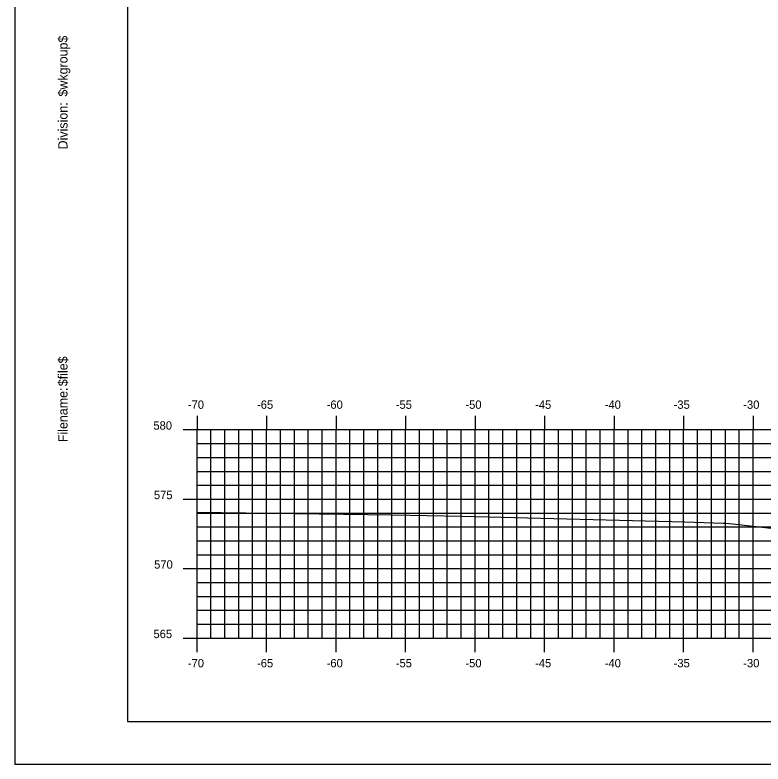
# Model space of a CAD drawing. Extents: x 1048552 to 1048722, y 781630 to 781740.
# Drawn here: x 1048552.2 to 1048606, y 781630.1 to 781684 of the extents above; entities that cross this region are included whole.
import ezdxf

# ---------------------------------------------------------------- set-up
doc = ezdxf.new("R2010")
doc.units = 0
for name, color, linetype in [('Default', 7, 'Continuous'), ('H_V ANNOTATION', 7, 'Continuous'), ('MAJOR', 7, 'Continuous'), ('MINOR', 7, 'Continuous'), ('S_Roadway_Centerline', 7, 'Continuous')]:
    doc.layers.add(name, color=color, linetype=linetype)

msp = doc.modelspace()

# ---------------------------------------------------------------- linework, layer by layer
at = {"layer": 'Default'}
for p, q in [((1048560.247, 781738.195), (1048560.247, 781633.195)), ((1048560.247, 781633.195), (1048720.247, 781633.195))]:
    msp.add_line(p, q, dxfattribs=at)
msp.add_lwpolyline([(1048552.153, 781630.136), (1048722.153, 781630.136), (1048722.153, 781740.136), (1048552.153, 781740.136)], close=True, dxfattribs=at)
at = {"layer": 'MAJOR'}
for p, q in [((1048565.246, 781655.197), (1048565.246, 781654.195)), ((1048565.246, 781655.197), (1048565.246, 781654.195)), ((1048570.246, 781655.197), (1048570.246, 781654.195)), ((1048570.246, 781655.197), (1048570.246, 781654.195)), ((1048575.246, 781655.197), (1048575.246, 781654.195)), ((1048575.246, 781655.197), (1048575.246, 781654.195)), ((1048580.246, 781655.197), (1048580.246, 781654.195)), ((1048580.246, 781655.197), (1048580.246, 781654.195)), ((1048585.246, 781655.197), (1048585.246, 781654.195)), ((1048585.246, 781655.197), (1048585.246, 781654.195)), ((1048590.246, 781655.197), (1048590.246, 781654.195)), ((1048590.246, 781655.197), (1048590.246, 781654.195)), ((1048595.246, 781655.197), (1048595.246, 781654.195)), ((1048595.246, 781655.197), (1048595.246, 781654.195)), ((1048600.246, 781655.197), (1048600.246, 781654.195)), ((1048600.246, 781655.197), (1048600.246, 781654.195)), ((1048605.246, 781655.197), (1048605.246, 781654.195)), ((1048605.246, 781655.197), (1048605.246, 781654.195)), ((1048564.244, 781654.195), (1048565.246, 781654.195)), ((1048564.244, 781654.195), (1048565.246, 781654.195)), ((1048565.246, 781654.195), (1048705.246, 781654.195)), ((1048565.246, 781639.195), (1048565.246, 781654.195)), ((1048565.246, 781639.195), (1048565.246, 781654.195)), ((1048565.246, 781654.195), (1048705.246, 781654.195)), ((1048565.246, 781654.195), (1048705.246, 781654.195)), ((1048565.246, 781639.195), (1048565.246, 781654.195)), ((1048565.246, 781639.195), (1048565.246, 781654.195)), ((1048565.246, 781654.195), (1048705.246, 781654.195)), ((1048570.246, 781639.195), (1048570.246, 781654.195)), ((1048570.246, 781639.195), (1048570.246, 781654.195)), ((1048575.246, 781639.195), (1048575.246, 781654.195)), ((1048575.246, 781639.195), (1048575.246, 781654.195)), ((1048580.246, 781639.195), (1048580.246, 781654.195)), ((1048580.246, 781639.195), (1048580.246, 781654.195)), ((1048585.246, 781639.195), (1048585.246, 781654.195)), ((1048585.246, 781639.195), (1048585.246, 781654.195)), ((1048590.246, 781639.195), (1048590.246, 781654.195)), ((1048590.246, 781639.195), (1048590.246, 781654.195)), ((1048595.246, 781639.195), (1048595.246, 781654.195)), ((1048595.246, 781639.195), (1048595.246, 781654.195)), ((1048600.246, 781639.195), (1048600.246, 781654.195)), ((1048600.246, 781639.195), (1048600.246, 781654.195)), ((1048605.246, 781639.195), (1048605.246, 781654.195)), ((1048605.246, 781639.195), (1048605.246, 781654.195)), ((1048564.244, 781649.195), (1048565.246, 781649.195)), ((1048564.244, 781649.195), (1048565.246, 781649.195)), ((1048565.246, 781649.195), (1048705.246, 781649.195)), ((1048565.246, 781649.195), (1048705.246, 781649.195)), ((1048564.244, 781644.195), (1048565.246, 781644.195)), ((1048564.244, 781644.195), (1048565.246, 781644.195)), ((1048565.246, 781644.195), (1048705.246, 781644.195)), ((1048565.246, 781644.195), (1048705.246, 781644.195)), ((1048564.244, 781639.195), (1048565.246, 781639.195)), ((1048564.244, 781639.195), (1048565.246, 781639.195)), ((1048565.246, 781639.195), (1048705.246, 781639.195)), ((1048565.246, 781639.195), (1048705.246, 781639.195)), ((1048565.246, 781638.193), (1048565.246, 781639.195)), ((1048565.246, 781639.195), (1048705.246, 781639.195)), ((1048565.246, 781639.195), (1048705.246, 781639.195)), ((1048565.246, 781638.193), (1048565.246, 781639.195)), ((1048570.246, 781638.193), (1048570.246, 781639.195)), ((1048570.246, 781638.193), (1048570.246, 781639.195)), ((1048575.246, 781638.193), (1048575.246, 781639.195)), ((1048575.246, 781638.193), (1048575.246, 781639.195)), ((1048580.246, 781638.193), (1048580.246, 781639.195)), ((1048580.246, 781638.193), (1048580.246, 781639.195)), ((1048585.246, 781638.193), (1048585.246, 781639.195)), ((1048585.246, 781638.193), (1048585.246, 781639.195)), ((1048590.246, 781638.193), (1048590.246, 781639.195)), ((1048590.246, 781638.193), (1048590.246, 781639.195)), ((1048595.246, 781638.193), (1048595.246, 781639.195)), ((1048595.246, 781638.193), (1048595.246, 781639.195)), ((1048600.246, 781638.193), (1048600.246, 781639.195)), ((1048600.246, 781638.193), (1048600.246, 781639.195)), ((1048605.246, 781638.193), (1048605.246, 781639.195)), ((1048605.246, 781638.193), (1048605.246, 781639.195))]:
    msp.add_line(p, q, dxfattribs=at)
at = {"layer": 'MINOR'}
for p, q in [((1048566.246, 781639.195), (1048566.246, 781654.195)), ((1048566.246, 781639.195), (1048566.246, 781654.195)), ((1048567.246, 781639.195), (1048567.246, 781654.195)), ((1048567.246, 781639.195), (1048567.246, 781654.195)), ((1048568.246, 781639.195), (1048568.246, 781654.195)), ((1048568.246, 781639.195), (1048568.246, 781654.195)), ((1048569.246, 781639.195), (1048569.246, 781654.195)), ((1048569.246, 781639.195), (1048569.246, 781654.195)), ((1048571.246, 781639.195), (1048571.246, 781654.195)), ((1048571.246, 781639.195), (1048571.246, 781654.195)), ((1048572.246, 781639.195), (1048572.246, 781654.195)), ((1048572.246, 781639.195), (1048572.246, 781654.195)), ((1048573.246, 781639.195), (1048573.246, 781654.195)), ((1048573.246, 781639.195), (1048573.246, 781654.195)), ((1048574.246, 781639.195), (1048574.246, 781654.195)), ((1048574.246, 781639.195), (1048574.246, 781654.195)), ((1048576.246, 781639.195), (1048576.246, 781654.195)), ((1048576.246, 781639.195), (1048576.246, 781654.195)), ((1048577.246, 781639.195), (1048577.246, 781654.195)), ((1048577.246, 781639.195), (1048577.246, 781654.195)), ((1048578.246, 781639.195), (1048578.246, 781654.195)), ((1048578.246, 781639.195), (1048578.246, 781654.195)), ((1048579.246, 781639.195), (1048579.246, 781654.195)), ((1048579.246, 781639.195), (1048579.246, 781654.195)), ((1048581.246, 781639.195), (1048581.246, 781654.195)), ((1048581.246, 781639.195), (1048581.246, 781654.195)), ((1048582.246, 781639.195), (1048582.246, 781654.195)), ((1048582.246, 781639.195), (1048582.246, 781654.195)), ((1048583.246, 781639.195), (1048583.246, 781654.195)), ((1048583.246, 781639.195), (1048583.246, 781654.195)), ((1048584.246, 781639.195), (1048584.246, 781654.195)), ((1048584.246, 781639.195), (1048584.246, 781654.195)), ((1048586.246, 781639.195), (1048586.246, 781654.195)), ((1048586.246, 781639.195), (1048586.246, 781654.195)), ((1048587.246, 781639.195), (1048587.246, 781654.195)), ((1048587.246, 781639.195), (1048587.246, 781654.195)), ((1048588.246, 781639.195), (1048588.246, 781654.195)), ((1048588.246, 781639.195), (1048588.246, 781654.195)), ((1048589.246, 781639.195), (1048589.246, 781654.195)), ((1048589.246, 781639.195), (1048589.246, 781654.195)), ((1048591.246, 781639.195), (1048591.246, 781654.195)), ((1048591.246, 781639.195), (1048591.246, 781654.195)), ((1048592.246, 781639.195), (1048592.246, 781654.195)), ((1048592.246, 781639.195), (1048592.246, 781654.195)), ((1048593.246, 781639.195), (1048593.246, 781654.195)), ((1048593.246, 781639.195), (1048593.246, 781654.195)), ((1048594.246, 781639.195), (1048594.246, 781654.195)), ((1048594.246, 781639.195), (1048594.246, 781654.195)), ((1048596.246, 781639.195), (1048596.246, 781654.195)), ((1048596.246, 781639.195), (1048596.246, 781654.195)), ((1048597.246, 781639.195), (1048597.246, 781654.195)), ((1048597.246, 781639.195), (1048597.246, 781654.195)), ((1048598.246, 781639.195), (1048598.246, 781654.195)), ((1048598.246, 781639.195), (1048598.246, 781654.195)), ((1048599.246, 781639.195), (1048599.246, 781654.195)), ((1048599.246, 781639.195), (1048599.246, 781654.195)), ((1048601.246, 781639.195), (1048601.246, 781654.195)), ((1048601.246, 781639.195), (1048601.246, 781654.195)), ((1048602.246, 781639.195), (1048602.246, 781654.195)), ((1048602.246, 781639.195), (1048602.246, 781654.195)), ((1048603.246, 781639.195), (1048603.246, 781654.195)), ((1048603.246, 781639.195), (1048603.246, 781654.195)), ((1048604.246, 781639.195), (1048604.246, 781654.195)), ((1048604.246, 781639.195), (1048604.246, 781654.195)), ((1048565.246, 781653.195), (1048705.246, 781653.195)), ((1048565.246, 781653.195), (1048566.248, 781653.195)), ((1048565.246, 781653.195), (1048705.246, 781653.195)), ((1048565.246, 781653.195), (1048566.248, 781653.195)), ((1048565.246, 781652.195), (1048705.246, 781652.195)), ((1048565.246, 781652.195), (1048566.248, 781652.195)), ((1048565.246, 781652.195), (1048705.246, 781652.195)), ((1048565.246, 781652.195), (1048566.248, 781652.195)), ((1048565.246, 781651.195), (1048705.246, 781651.195)), ((1048565.246, 781651.195), (1048566.248, 781651.195)), ((1048565.246, 781651.195), (1048705.246, 781651.195)), ((1048565.246, 781651.195), (1048566.248, 781651.195)), ((1048565.246, 781650.195), (1048705.246, 781650.195)), ((1048565.246, 781650.195), (1048566.248, 781650.195)), ((1048565.246, 781650.195), (1048705.246, 781650.195)), ((1048565.246, 781650.195), (1048566.248, 781650.195)), ((1048565.246, 781648.195), (1048705.246, 781648.195)), ((1048565.246, 781648.195), (1048566.248, 781648.195)), ((1048565.246, 781648.195), (1048705.246, 781648.195)), ((1048565.246, 781648.195), (1048566.248, 781648.195)), ((1048565.246, 781647.195), (1048705.246, 781647.195)), ((1048565.246, 781647.195), (1048566.248, 781647.195)), ((1048565.246, 781647.195), (1048705.246, 781647.195)), ((1048565.246, 781647.195), (1048566.248, 781647.195)), ((1048565.246, 781646.195), (1048705.246, 781646.195)), ((1048565.246, 781646.195), (1048566.248, 781646.195)), ((1048565.246, 781646.195), (1048705.246, 781646.195)), ((1048565.246, 781646.195), (1048566.248, 781646.195)), ((1048565.246, 781645.195), (1048705.246, 781645.195)), ((1048565.246, 781645.195), (1048566.248, 781645.195)), ((1048565.246, 781645.195), (1048705.246, 781645.195)), ((1048565.246, 781645.195), (1048566.248, 781645.195)), ((1048565.246, 781643.195), (1048705.246, 781643.195)), ((1048565.246, 781643.195), (1048566.248, 781643.195)), ((1048565.246, 781643.195), (1048705.246, 781643.195)), ((1048565.246, 781643.195), (1048566.248, 781643.195)), ((1048565.246, 781642.195), (1048705.246, 781642.195)), ((1048565.246, 781642.195), (1048566.248, 781642.195)), ((1048565.246, 781642.195), (1048705.246, 781642.195)), ((1048565.246, 781642.195), (1048566.248, 781642.195)), ((1048565.246, 781641.195), (1048705.246, 781641.195)), ((1048565.246, 781641.195), (1048566.248, 781641.195)), ((1048565.246, 781641.195), (1048705.246, 781641.195)), ((1048565.246, 781641.195), (1048566.248, 781641.195)), ((1048565.246, 781640.195), (1048705.246, 781640.195)), ((1048565.246, 781640.195), (1048566.248, 781640.195)), ((1048565.246, 781640.195), (1048705.246, 781640.195)), ((1048565.246, 781640.195), (1048566.248, 781640.195))]:
    msp.add_line(p, q, dxfattribs=at)
at = {"layer": 'S_Roadway_Centerline'}
msp.add_lwpolyline([(1048565.246, 781648.25), (1048579.277, 781648.059), (1048584.319, 781647.976), (1048600.326, 781647.557), (1048603.089, 781647.473), (1048603.286, 781647.461), (1048603.755, 781647.418), (1048616.956, 781645.932), (1048618.792, 781645.68), (1048619.828, 781645.755), (1048620.204, 781645.767), (1048632.993, 781646.121), (1048633.16, 781646.13), (1048635.318, 781646.203), (1048637.477, 781646.138), (1048649.509, 781645.9), (1048649.801, 781645.635), (1048650.76, 781645.672), (1048653.408, 781645.769), (1048655.135, 781645.053), (1048656.757, 781644.536)], dxfattribs=at)

# ---------------------------------------------------------------- texts
at = {"layer": 'Default'}
for s, p in [('$wkgroup$', (1048555.932, 781678.165)), ('Division:', (1048555.932, 781674.362)), ('$file$', (1048555.932, 781657.321)), ('Filename:', (1048555.932, 781653.294))]:
    msp.add_text(s, height=0.6696, rotation=90, dxfattribs=at).set_placement(p)
at = {"layer": 'H_V ANNOTATION'}
for s, p in [('-70', (1048564.588, 781655.695)), ('-65', (1048569.564, 781655.695)), ('-60', (1048574.572, 781655.695)), ('-55', (1048579.543, 781655.695)), ('-50', (1048584.551, 781655.695)), ('-45', (1048589.564, 781655.695)), ('-40', (1048594.572, 781655.695)), ('-35', (1048599.527, 781655.695)), ('-30', (1048604.535, 781655.695)), ('580', (1048562.108, 781654.195)), ('575', (1048562.146, 781649.195)), ('570', (1048562.162, 781644.195)), ('565', (1048562.114, 781639.195)), ('-70', (1048564.588, 781637.095)), ('-65', (1048569.564, 781637.095)), ('-60', (1048574.572, 781637.095)), ('-55', (1048579.543, 781637.095)), ('-50', (1048584.551, 781637.095)), ('-45', (1048589.564, 781637.095)), ('-40', (1048594.572, 781637.095)), ('-35', (1048599.527, 781637.095)), ('-30', (1048604.535, 781637.095))]:
    msp.add_text(s, height=0.6, dxfattribs=at).set_placement(p)
at = {"layer": 'MAJOR'}
msp.add_text('-', height=0.006, dxfattribs=at).set_placement((1048565.242, 781639.195))
msp.add_text('-', height=0.006, dxfattribs=at).set_placement((1048565.242, 781639.195))

doc.saveas('drawing.dxf')
